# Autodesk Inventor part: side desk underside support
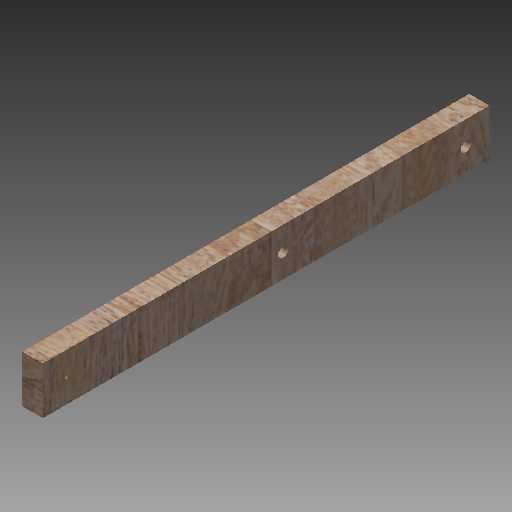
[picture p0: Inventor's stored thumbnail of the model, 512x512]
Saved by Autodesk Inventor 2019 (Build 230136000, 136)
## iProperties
Created: 2013-07
Part Number: side desk underside support
Material: Generic
Document SubType Name: Modeling
Designer: Patrick Rice
Density: 1 g/cm^3
Appearance: Red Oak - Natural
Author: Patrick Rice
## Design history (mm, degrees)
sketch "Sketch1"
  geometry: L1 (19.05, -44.45)-(-19.05, -44.45); L2 (-19.05, -44.45)-(-19.05, 44.45); L3 (-19.05, 44.45)-(19.05, 44.45); L4 (19.05, 44.45)-(19.05, -44.45); L5 (19.05, -44.45)-(-19.05, 44.45); L6 (-19.05, -44.45)-(19.05, 44.45); 1 further point
  constraints: 12 end point, 2 midpoint, 2 parallel, 1 horizontal, 1 perpendicular
  dimensions: "d0" = 38.1 distance of L2.end L3.end; "d1" = 88.9 distance of L1.end L2.end
extrude "Extrusion1" new body sketch "Sketch1" distance "d2" = 838.2; taper "d3" = 0 deg
hole "Hole3" diameter "d24" = 6.35; stored, may be unused: countersink angle "d28" = 82 deg, drill point angle "d30" = 118 deg; dims "d22" = 44.45, "d23" = 44.45, "d25" = 19.05, "d26" = 9.525, "d27" = 6.35, "d29" = 25.4
hole "Hole4" diameter "d33" = 6.35; stored, may be unused: countersink angle "d37" = 82 deg, drill point angle "d39" = 118 deg; dims "d32" = 387.35, "d34" = 19.05, "d35" = 19.05, "d36" = 12.7, "d38" = 25.4, "d40" = 44.45
hole "Hole5" diameter "d43" = 6.35; stored, may be unused: countersink angle "d47" = 82 deg, drill point angle "d49" = 118 deg; dims "d42" = 44.45, "d44" = 19.05, "d45" = 19.05, "d46" = 12.7, "d48" = 25.4, "d50" = 44.45
body "Solid1"
